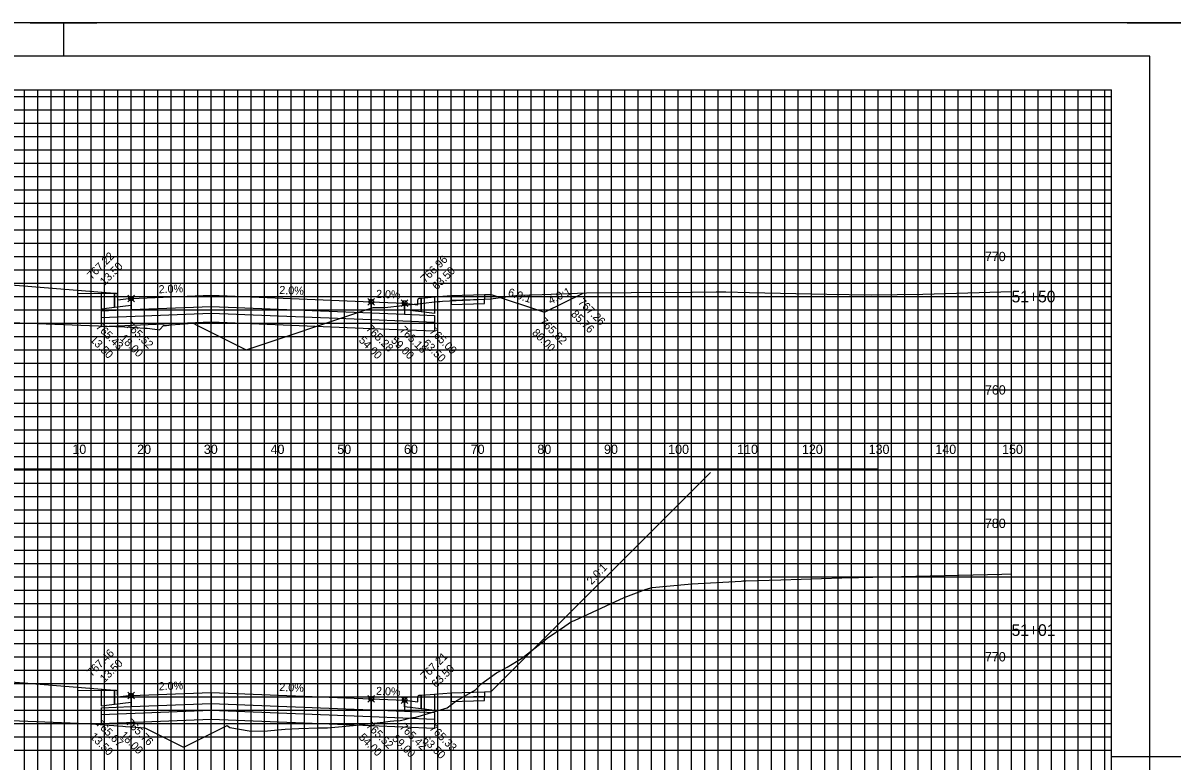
# Model space of a CAD drawing. Extents: x 578243 to 601557, y 174899 to 175559.
# Drawn here: x 601041.6 to 601213.9, y 175008.2 to 175118.8 of the extents above; entities that cross this region are included whole.
import ezdxf

# ---------------------------------------------------------------- set-up
doc = ezdxf.new("R2010")
doc.units = 0
for name, color, linetype in [('E_PROF_Grid', 7, 'Continuous'), ('E_PROF_GridMin', 7, 'Continuous'), ('P_CRDR_Label', 7, 'Continuous'), ('P_CRDR_Link', 7, 'Continuous'), ('P_E_XS_Ground', 7, 'Continuous'), ('P_RW_SlopeIntercepts', 7, 'Continuous'), ('P_XS_Text', 7, 'Continuous'), ('PLT_Sheet_Border', 7, 'Continuous'), ('PLT_Sheet_Info', 7, 'Continuous')]:
    doc.layers.add(name, color=color, linetype=linetype)

msp = doc.modelspace()

# ---------------------------------------------------------------- linework, layer by layer
at = {"layer": 'E_PROF_Grid'}
for p, q in [((601049.84, 174913.8), (601049.84, 175108.8)), ((601059.84, 174913.8), (601059.84, 175108.8)), ((601069.84, 174913.8), (601069.84, 175108.8)), ((601079.84, 174913.8), (601079.84, 175108.8)), ((601089.84, 174913.8), (601089.84, 175108.8)), ((601099.84, 174913.8), (601099.84, 175108.8)), ((601109.84, 174913.8), (601109.84, 175108.8)), ((601119.84, 174913.8), (601119.84, 175108.8)), ((601129.84, 174913.8), (601129.84, 175108.8)), ((601139.84, 174913.8), (601139.84, 175108.8)), ((601149.84, 174913.8), (601149.84, 175108.8)), ((601159.84, 174913.8), (601159.84, 175108.8)), ((601169.84, 174913.8), (601169.84, 175108.8)), ((601179.84, 174913.8), (601179.84, 175108.8)), ((601189.84, 174913.8), (601189.84, 175108.8)), ((601199.84, 174913.8), (601199.84, 175108.8)), ((600889.84, 175103.8), (601204.84, 175103.8)), ((600889.84, 175093.8), (601204.84, 175093.8)), ((600889.84, 175083.8), (601204.84, 175083.8)), ((600889.84, 175073.8), (601204.84, 175073.8)), ((600889.84, 175063.8), (601204.84, 175063.8)), ((600889.84, 175053.8), (601204.84, 175053.8)), ((600889.84, 175043.8), (601204.84, 175043.8)), ((600889.84, 175033.8), (601204.84, 175033.8)), ((600889.84, 175023.8), (601204.84, 175023.8)), ((600889.84, 175013.8), (601204.84, 175013.8))]:
    msp.add_line(p, q, dxfattribs=at)
at = {"layer": 'E_PROF_GridMin'}
for p, q in [((601041.84, 174913.8), (601041.84, 175108.8)), ((601043.84, 174913.8), (601043.84, 175108.8)), ((601045.84, 174913.8), (601045.84, 175108.8)), ((601047.84, 174913.8), (601047.84, 175108.8)), ((601051.84, 174913.8), (601051.84, 175108.8)), ((601053.84, 174913.8), (601053.84, 175108.8)), ((601055.84, 174913.8), (601055.84, 175108.8)), ((601057.84, 174913.8), (601057.84, 175108.8)), ((601061.84, 174913.8), (601061.84, 175108.8)), ((601063.84, 174913.8), (601063.84, 175108.8)), ((601065.84, 174913.8), (601065.84, 175108.8)), ((601067.84, 174913.8), (601067.84, 175108.8)), ((601071.84, 174913.8), (601071.84, 175108.8)), ((601073.84, 174913.8), (601073.84, 175108.8)), ((601075.84, 174913.8), (601075.84, 175108.8)), ((601077.84, 174913.8), (601077.84, 175108.8)), ((601081.84, 174913.8), (601081.84, 175108.8)), ((601083.84, 174913.8), (601083.84, 175108.8)), ((601085.84, 174913.8), (601085.84, 175108.8)), ((601087.84, 174913.8), (601087.84, 175108.8)), ((601091.84, 174913.8), (601091.84, 175108.8)), ((601093.84, 174913.8), (601093.84, 175108.8)), ((601095.84, 174913.8), (601095.84, 175108.8)), ((601097.84, 174913.8), (601097.84, 175108.8)), ((601101.84, 174913.8), (601101.84, 175108.8)), ((601103.84, 174913.8), (601103.84, 175108.8)), ((601105.84, 174913.8), (601105.84, 175108.8)), ((601107.84, 174913.8), (601107.84, 175108.8)), ((601111.84, 174913.8), (601111.84, 175108.8)), ((601113.84, 174913.8), (601113.84, 175108.8)), ((601115.84, 174913.8), (601115.84, 175108.8)), ((601117.84, 174913.8), (601117.84, 175108.8)), ((601121.84, 174913.8), (601121.84, 175108.8)), ((601123.84, 174913.8), (601123.84, 175108.8)), ((601125.84, 174913.8), (601125.84, 175108.8)), ((601127.84, 174913.8), (601127.84, 175108.8)), ((601131.84, 174913.8), (601131.84, 175108.8)), ((601133.84, 174913.8), (601133.84, 175108.8)), ((601135.84, 174913.8), (601135.84, 175108.8)), ((601137.84, 174913.8), (601137.84, 175108.8)), ((601141.84, 174913.8), (601141.84, 175108.8)), ((601143.84, 174913.8), (601143.84, 175108.8)), ((601145.84, 174913.8), (601145.84, 175108.8)), ((601147.84, 174913.8), (601147.84, 175108.8)), ((601151.84, 174913.8), (601151.84, 175108.8)), ((601153.84, 174913.8), (601153.84, 175108.8)), ((601155.84, 174913.8), (601155.84, 175108.8)), ((601157.84, 174913.8), (601157.84, 175108.8)), ((601161.84, 174913.8), (601161.84, 175108.8)), ((601163.84, 174913.8), (601163.84, 175108.8)), ((601165.84, 174913.8), (601165.84, 175108.8)), ((601167.84, 174913.8), (601167.84, 175108.8)), ((601171.84, 174913.8), (601171.84, 175108.8)), ((601173.84, 174913.8), (601173.84, 175108.8)), ((601175.84, 174913.8), (601175.84, 175108.8)), ((601177.84, 174913.8), (601177.84, 175108.8)), ((601181.84, 174913.8), (601181.84, 175108.8)), ((601183.84, 174913.8), (601183.84, 175108.8)), ((601185.84, 174913.8), (601185.84, 175108.8)), ((601187.84, 174913.8), (601187.84, 175108.8)), ((601191.84, 174913.8), (601191.84, 175108.8)), ((601193.84, 174913.8), (601193.84, 175108.8)), ((601195.84, 174913.8), (601195.84, 175108.8)), ((601197.84, 174913.8), (601197.84, 175108.8)), ((601201.84, 174913.8), (601201.84, 175108.8)), ((601203.84, 174913.8), (601203.84, 175108.8)), ((600889.84, 175107.8), (601204.84, 175107.8)), ((600889.84, 175105.8), (601204.84, 175105.8)), ((600889.84, 175101.8), (601204.84, 175101.8)), ((600889.84, 175099.8), (601204.84, 175099.8)), ((600889.84, 175097.8), (601204.84, 175097.8)), ((600889.84, 175095.8), (601204.84, 175095.8)), ((600889.84, 175091.8), (601204.84, 175091.8)), ((600889.84, 175089.8), (601204.84, 175089.8)), ((600889.84, 175087.8), (601204.84, 175087.8)), ((600889.84, 175085.8), (601204.84, 175085.8)), ((600889.84, 175081.8), (601204.84, 175081.8)), ((600889.84, 175079.8), (601204.84, 175079.8)), ((600889.84, 175077.8), (601204.84, 175077.8)), ((600889.84, 175075.8), (601204.84, 175075.8)), ((600889.84, 175071.8), (601204.84, 175071.8)), ((600889.84, 175069.8), (601204.84, 175069.8)), ((600889.84, 175067.8), (601204.84, 175067.8)), ((600889.84, 175065.8), (601204.84, 175065.8)), ((600889.84, 175061.8), (601204.84, 175061.8)), ((600889.84, 175059.8), (601204.84, 175059.8)), ((600889.84, 175057.8), (601204.84, 175057.8)), ((600889.84, 175055.8), (601204.84, 175055.8)), ((600889.84, 175051.8), (601204.84, 175051.8)), ((600889.84, 175049.8), (601204.84, 175049.8)), ((600889.84, 175047.8), (601204.84, 175047.8)), ((600889.84, 175045.8), (601204.84, 175045.8)), ((600889.84, 175041.8), (601204.84, 175041.8)), ((600889.84, 175039.8), (601204.84, 175039.8)), ((600889.84, 175037.8), (601204.84, 175037.8)), ((600889.84, 175035.8), (601204.84, 175035.8)), ((600889.84, 175031.8), (601204.84, 175031.8)), ((600889.84, 175029.8), (601204.84, 175029.8)), ((600889.84, 175027.8), (601204.84, 175027.8)), ((600889.84, 175025.8), (601204.84, 175025.8)), ((600889.84, 175021.8), (601204.84, 175021.8)), ((600889.84, 175019.8), (601204.84, 175019.8)), ((600889.84, 175017.8), (601204.84, 175017.8)), ((600889.84, 175015.8), (601204.84, 175015.8)), ((600889.84, 175011.8), (601204.84, 175011.8)), ((600889.84, 175009.8), (601204.84, 175009.8))]:
    msp.add_line(p, q, dxfattribs=at)
at = {"layer": 'P_CRDR_Label'}
for points in [[(601057.34, 175077), (601058.33, 175077.99)], [(601057.34, 175077.99), (601058.33, 175077)], [(601093.34, 175076.52), (601094.33, 175077.51)], [(601093.34, 175077.51), (601094.33, 175076.52)], [(601098.34, 175076.32), (601099.33, 175077.31)], [(601098.34, 175077.31), (601099.33, 175076.32)], [(601057.34, 175017.49), (601058.33, 175018.48)], [(601057.34, 175018.48), (601058.33, 175017.49)], [(601093.34, 175017.01), (601094.33, 175018)], [(601093.34, 175018), (601094.33, 175017.01)], [(601098.34, 175016.81), (601099.33, 175017.8)], [(601098.34, 175017.8), (601099.33, 175016.81)]]:
    msp.add_lwpolyline(points, dxfattribs=at)
for centre in [(601057.84, 175077.5), (601093.84, 175077.02), (601098.84, 175076.82), (601057.84, 175017.98), (601093.84, 175017.5), (601098.84, 175017.3)]:
    msp.add_circle(centre, 0.35, dxfattribs=at)
at = {"layer": 'P_CRDR_Link'}
msp.add_line((601144.69, 175051.44), (601111.84, 175018.59), dxfattribs=at)
for points in [[(601055.34, 175078.25), (601039.84, 175079.49)], [(601055.34, 175078.25), (601039.84, 175079.49)], [(601053.34, 175078.23), (601049.84, 175078.2)], [(601053.34, 175078.23), (601049.84, 175078.2)], [(601055.34, 175078.25), (601053.34, 175078.23)], [(601053.34, 175078.23), (601053.34, 175075.93)], [(601053.34, 175078.23), (601053.34, 175075.93)], [(601053.34, 175078.23), (601053.34, 175075.93)], [(601055.66, 175078.25), (601055.34, 175078.25)], [(601055.66, 175078.25), (601055.34, 175078.25)], [(601055.34, 175078.25), (601055.34, 175076.18)], [(601055.34, 175076.18), (601055.34, 175078.25)], [(601055.74, 175078.2), (601055.66, 175078.25)], [(601055.74, 175078.2), (601055.66, 175078.25)], [(601055.8, 175078.09), (601055.74, 175078.2)], [(601055.8, 175078.09), (601055.74, 175078.2)], [(601055.83, 175077.93), (601055.8, 175078.09)], [(601055.83, 175077.93), (601055.8, 175078.09)], [(601055.84, 175077.25), (601055.83, 175077.93)], [(601055.84, 175077.25), (601055.83, 175077.93)], [(601057.84, 175077.5), (601069.84, 175077.98)], [(601069.84, 175077.98), (601069.84, 175076.31)], [(601069.84, 175077.98), (601093.84, 175077.02)], [(601069.84, 175077.98), (601069.84, 175076.31)], [(601101.34, 175077.57), (601103.34, 175077.73)], [(601103.34, 175077.73), (601105.84, 175077.93)], [(601103.34, 175077.73), (601105.84, 175077.93)], [(601103.34, 175077.73), (601103.34, 175075.25)], [(601103.34, 175077.73), (601103.34, 175075.25)], [(601103.34, 175077.73), (601103.34, 175075.25)], [(601105.84, 175077.93), (601110.84, 175078.08)], [(601105.84, 175077.93), (601110.84, 175078.08)], [(601105.84, 175077.93), (601105.84, 175077.26)], [(601110.84, 175078.08), (601110.83, 175077.41)], [(601110.84, 175078.08), (601111.84, 175078.11)], [(601110.84, 175078.08), (601111.84, 175078.11)], [(601111.84, 175078.11), (601119.84, 175075.44)], [(601111.84, 175078.11), (601119.84, 175075.44)], [(601119.84, 175075.44), (601125.6, 175078.32)], [(601119.84, 175075.44), (601125.6, 175078.32)], [(601053.34, 175075.93), (601055.34, 175076.18)], [(601055.34, 175076.18), (601057.84, 175076.5)], [(601055.34, 175076.18), (601057.84, 175076.5)], [(601057.84, 175077.5), (601055.84, 175077.25)], [(601057.84, 175077.5), (601055.84, 175077.25)], [(601057.84, 175076.5), (601057.84, 175077.5)], [(601057.84, 175077.5), (601057.84, 175075.83)], [(601057.84, 175075.83), (601069.84, 175076.31)], [(601069.84, 175076.31), (601069.84, 175075.31)], [(601069.84, 175076.31), (601093.84, 175075.35)], [(601069.84, 175076.31), (601069.84, 175075.31)], [(601093.84, 175077.02), (601093.84, 175075.35)], [(601093.84, 175077.02), (601098.84, 175076.82)], [(601093.84, 175077.02), (601093.84, 175075.35)], [(601098.84, 175076.82), (601098.84, 175075.15)], [(601098.84, 175076.82), (601100.84, 175076.57)], [(601098.84, 175076.82), (601100.84, 175076.57)], [(601098.84, 175075.82), (601098.84, 175076.82)], [(601100.84, 175076.57), (601100.85, 175077.25)], [(601100.84, 175076.57), (601100.85, 175077.25)], [(601100.85, 175077.25), (601100.88, 175077.41)], [(601100.85, 175077.25), (601100.88, 175077.41)], [(601100.88, 175077.41), (601100.94, 175077.52)], [(601100.88, 175077.41), (601100.94, 175077.52)], [(601100.94, 175077.52), (601101.02, 175077.57)], [(601100.94, 175077.52), (601101.02, 175077.57)], [(601101.02, 175077.57), (601101.34, 175077.57)], [(601101.02, 175077.57), (601101.34, 175077.57)], [(601101.34, 175077.57), (601101.34, 175075.5)], [(601101.34, 175075.5), (601101.34, 175077.57)], [(601105.84, 175077.26), (601110.83, 175077.41)], [(601105.84, 175077.26), (601105.85, 175076.6)], [(601105.85, 175076.6), (601110.83, 175076.75)], [(601110.83, 175076.75), (601110.83, 175077.41)], [(601053.34, 175075.65), (601057.84, 175075.83)], [(601053.34, 175075.65), (601053.34, 175074.65)], [(601053.34, 175074.65), (601069.84, 175075.31)], [(601053.34, 175074.65), (601053.34, 175073.32)], [(601069.84, 175075.31), (601069.84, 175073.98)], [(601069.84, 175075.31), (601093.84, 175074.35)], [(601069.84, 175075.31), (601069.84, 175073.98)], [(601093.84, 175075.35), (601093.84, 175074.35)], [(601093.84, 175075.35), (601098.84, 175075.15)], [(601093.84, 175075.35), (601093.84, 175074.35)], [(601093.84, 175074.35), (601093.84, 175073.02)], [(601093.84, 175074.35), (601103.34, 175073.97)], [(601093.84, 175074.35), (601093.84, 175073.02)], [(601101.34, 175075.5), (601098.84, 175075.82)], [(601101.34, 175075.5), (601098.84, 175075.82)], [(601098.84, 175075.15), (601103.34, 175074.97)], [(601103.34, 175075.25), (601101.34, 175075.5)], [(601103.34, 175074.97), (601103.34, 175073.97)], [(601053.34, 175073.32), (601069.84, 175073.98)], [(601069.84, 175073.98), (601093.84, 175073.02)], [(601093.84, 175073.02), (601103.34, 175072.64)], [(601103.34, 175073.97), (601103.34, 175072.64)], [(601055.34, 175018.73), (601039.84, 175019.97)], [(601055.34, 175018.73), (601039.84, 175019.97)], [(601053.34, 175018.72), (601049.84, 175018.69)], [(601053.34, 175018.72), (601049.84, 175018.69)], [(601055.34, 175018.73), (601053.34, 175018.72)], [(601053.34, 175018.72), (601053.34, 175016.42)], [(601053.34, 175018.72), (601053.34, 175016.42)], [(601053.34, 175018.72), (601053.34, 175016.42)], [(601055.66, 175018.73), (601055.34, 175018.73)], [(601055.66, 175018.73), (601055.34, 175018.73)], [(601055.34, 175018.73), (601055.34, 175016.67)], [(601055.34, 175016.67), (601055.34, 175018.73)], [(601055.74, 175018.69), (601055.66, 175018.73)], [(601055.74, 175018.69), (601055.66, 175018.73)], [(601055.8, 175018.57), (601055.74, 175018.69)], [(601055.8, 175018.57), (601055.74, 175018.69)], [(601055.83, 175018.41), (601055.8, 175018.57)], [(601055.83, 175018.41), (601055.8, 175018.57)], [(601055.84, 175017.73), (601055.83, 175018.41)], [(601055.84, 175017.73), (601055.83, 175018.41)], [(601057.84, 175017.98), (601055.84, 175017.73)], [(601057.84, 175017.98), (601055.84, 175017.73)], [(601057.84, 175017.98), (601069.84, 175018.46)], [(601057.84, 175016.98), (601057.84, 175017.98)], [(601057.84, 175017.98), (601057.84, 175016.32)], [(601069.84, 175018.46), (601069.84, 175016.8)], [(601069.84, 175018.46), (601093.84, 175017.5)], [(601069.84, 175018.46), (601069.84, 175016.8)], [(601093.84, 175017.5), (601093.84, 175015.84)], [(601093.84, 175017.5), (601098.84, 175017.3)], [(601093.84, 175017.5), (601093.84, 175015.84)], [(601100.84, 175017.05), (601100.85, 175017.73)], [(601100.84, 175017.05), (601100.85, 175017.73)], [(601100.85, 175017.73), (601100.88, 175017.89)], [(601100.85, 175017.73), (601100.88, 175017.89)], [(601100.88, 175017.89), (601100.94, 175018.01)], [(601100.88, 175017.89), (601100.94, 175018.01)], [(601100.94, 175018.01), (601101.02, 175018.05)], [(601100.94, 175018.01), (601101.02, 175018.05)], [(601101.02, 175018.05), (601101.34, 175018.05)], [(601101.02, 175018.05), (601101.34, 175018.05)], [(601101.34, 175018.05), (601103.34, 175018.21)], [(601101.34, 175018.05), (601101.34, 175015.99)], [(601101.34, 175015.99), (601101.34, 175018.05)], [(601103.34, 175018.21), (601105.84, 175018.41)], [(601103.34, 175018.21), (601105.84, 175018.41)], [(601103.34, 175018.21), (601103.34, 175015.74)], [(601103.34, 175018.21), (601103.34, 175015.74)], [(601103.34, 175018.21), (601103.34, 175015.74)], [(601105.84, 175018.41), (601110.84, 175018.56)], [(601105.84, 175018.41), (601110.84, 175018.56)], [(601105.84, 175018.41), (601105.84, 175017.75)], [(601105.84, 175017.75), (601110.83, 175017.9)], [(601105.84, 175017.75), (601105.85, 175017.08)], [(601110.84, 175018.56), (601110.83, 175017.9)], [(601110.83, 175017.23), (601110.83, 175017.9)], [(601110.84, 175018.56), (601111.84, 175018.59)], [(601110.84, 175018.56), (601111.84, 175018.59)], [(601053.34, 175016.42), (601055.34, 175016.67)], [(601053.34, 175016.14), (601057.84, 175016.32)], [(601053.34, 175016.14), (601053.34, 175015.14)], [(601053.34, 175015.14), (601069.84, 175015.8)], [(601055.34, 175016.67), (601057.84, 175016.98)], [(601055.34, 175016.67), (601057.84, 175016.98)], [(601057.84, 175016.32), (601069.84, 175016.8)], [(601069.84, 175016.8), (601069.84, 175015.8)], [(601069.84, 175016.8), (601093.84, 175015.84)], [(601069.84, 175016.8), (601069.84, 175015.8)], [(601069.84, 175015.8), (601069.84, 175014.46)], [(601069.84, 175015.8), (601093.84, 175014.84)], [(601069.84, 175015.8), (601069.84, 175014.46)], [(601093.84, 175015.84), (601093.84, 175014.84)], [(601093.84, 175015.84), (601098.84, 175015.64)], [(601093.84, 175015.84), (601093.84, 175014.84)], [(601098.84, 175017.3), (601098.84, 175015.64)], [(601098.84, 175017.3), (601100.84, 175017.05)], [(601098.84, 175017.3), (601100.84, 175017.05)], [(601098.84, 175016.3), (601098.84, 175017.3)], [(601101.34, 175015.99), (601098.84, 175016.3)], [(601101.34, 175015.99), (601098.84, 175016.3)], [(601103.34, 175015.74), (601101.34, 175015.99)], [(601105.85, 175017.08), (601110.83, 175017.23)], [(601053.34, 175015.14), (601053.34, 175013.8)], [(601053.34, 175013.8), (601069.84, 175014.46)], [(601069.84, 175014.46), (601093.84, 175013.5)], [(601093.84, 175014.84), (601093.84, 175013.5)], [(601093.84, 175014.84), (601103.34, 175014.46)], [(601093.84, 175014.84), (601093.84, 175013.5)], [(601098.84, 175015.64), (601103.34, 175015.46)], [(601103.34, 175015.46), (601103.34, 175014.46)], [(601103.34, 175014.46), (601103.34, 175013.12)], [(601093.84, 175013.5), (601103.34, 175013.12)]]:
    msp.add_lwpolyline(points, dxfattribs=at)
at = {"layer": 'P_E_XS_Ground'}
for points in [[(601039.84, 175073.91), (601056.84, 175073.23), (601059.95, 175073.07), (601059.95, 175073.07), (601060.06, 175073.06), (601060.12, 175073.06), (601060.14, 175073.06), (601060.26, 175073.04), (601062.14, 175072.81), (601062.15, 175072.83), (601062.72, 175073.47), (601063.13, 175073.47), (601063.14, 175073.47), (601063.84, 175073.53), (601065.1, 175073.63), (601065.15, 175073.63), (601067.05, 175073.78), (601067.16, 175073.79), (601067.82, 175073.45), (601075.09, 175069.83), (601092.59, 175075.66), (601094.15, 175076.17), (601094.36, 175076.17), (601095.9, 175076.17), (601103.85, 175077.04), (601104.11, 175077.05), (601104.51, 175077.08), (601111.79, 175077.44), (601115.88, 175077.98), (601119.49, 175078.11), (601126.1, 175078.34), (601132.83, 175078.42), (601141.98, 175078.43), (601145.54, 175078.52), (601147, 175078.51), (601150.54, 175078.41), (601162.14, 175078.14), (601168.84, 175078.04), (601176.52, 175078.17), (601184.96, 175078.41), (601189.84, 175078.55)], [(601039.84, 175014.25), (601051.19, 175013.79), (601051.84, 175013.77), (601056.62, 175013.38), (601056.99, 175013.35), (601059.83, 175013.13), (601059.99, 175013.11), (601061.22, 175012.5), (601061.28, 175012.47), (601065.39, 175010.42), (601065.62, 175010.3), (601065.66, 175010.29), (601065.84, 175010.28), (601071.45, 175013.09), (601072.24, 175013.49), (601072.66, 175013.22), (601075.53, 175012.72), (601077.72, 175012.67), (601080.92, 175012.97), (601082.98, 175013.06), (601085.94, 175013.15), (601087.29, 175013.13), (601091.11, 175013.51), (601095.61, 175014.01), (601096.69, 175014.14), (601097.22, 175014.18), (601098.18, 175014.25), (601098.89, 175014.4), (601099.55, 175014.58), (601100.07, 175014.69), (601100.53, 175014.77), (601100.54, 175014.77), (601101.38, 175014.98), (601105.21, 175016.15), (601106.52, 175017.13), (601109.47, 175018.86), (601110.28, 175019.67), (601112.61, 175021.38), (601114.24, 175022.25), (601116.36, 175023.56), (601119.31, 175025.84), (601120.24, 175026.57), (601122.87, 175028.4), (601123.89, 175029.06), (601124.31, 175029.22), (601131.76, 175032.69), (601135.06, 175033.91), (601135.94, 175034.17), (601141.35, 175034.7), (601141.97, 175034.73), (601149.29, 175035.15), (601149.56, 175035.16), (601149.98, 175035.17), (601155.27, 175035.34), (601164.39, 175035.63), (601165.57, 175035.66), (601166.87, 175035.69), (601188.39, 175036.2), (601189.84, 175036.25)]]:
    msp.add_lwpolyline(points, dxfattribs=at)
at = {"layer": 'P_RW_SlopeIntercepts'}
msp.add_line((600933.84, 175051.96), (601169.84, 175051.96), dxfattribs=at)
at = {"layer": 'PLT_Sheet_Border'}
for points in [[(600877.19, 174898.8), (601217.19, 174898.8), (601217.19, 175118.8), (600877.19, 175118.8)], [(600879.59, 174903.8), (601210.59, 174903.8), (601210.59, 175113.8), (600879.59, 175113.8)]]:
    msp.add_lwpolyline(points, close=True, dxfattribs=at)
at = {"layer": 'PLT_Sheet_Info'}
for p, q in [((601042.69, 175118.8), (601052.69, 175118.8)), ((601047.69, 175118.8), (601047.69, 175113.8)), ((601207.19, 175118.8), (601217.19, 175118.8)), ((600889.84, 175108.8), (601204.84, 175108.8)), ((601204.84, 174908.8), (601204.84, 175108.8)), ((601217.19, 175008.8), (601204.84, 175008.8))]:
    msp.add_line(p, q, dxfattribs=at)

# ---------------------------------------------------------------- texts
at = {"layer": 'P_CRDR_Label'}
for s, rotation, p in [('767.22', 45, (601051.93, 175080.27)), ('13.50', 45, (601053.87, 175079.39)), ('766.96', 45, (601101.93, 175079.77)), ('63.50', 45, (601103.69, 175078.71)), ('2.0%', 2.2906, (601062, 175078.28)), ('2.0%', 357.7094, (601080.05, 175078.19)), ('2.0%', 357.7094, (601094.55, 175077.61)), ('6.0:1', 341.5651, (601114.24, 175077.96)), ('4.0:1', 26.5651, (601120.74, 175076.59)), ('767.26', 315, (601124.75, 175076.84)), ('767.26', 315, (601124.75, 175076.84)), ('765.82', 315, (601118.99, 175073.96)), ('85.76', 315, (601123.72, 175075.05)), ('85.76', 315, (601123.72, 175075.05)), ('765.43', 315, (601052.49, 175073.17)), ('765.52', 315, (601056.99, 175073.35)), ('765.28', 315, (601092.99, 175072.87)), ('765.18', 315, (601097.99, 175072.67)), ('765.09', 315, (601102.49, 175072.49)), ('80.00', 315, (601117.87, 175072.26)), ('13.50', 315, (601051.6, 175071.23)), ('18.00', 315, (601056.08, 175071.44)), ('54.00', 315, (601091.9, 175071.14)), ('59.00', 315, (601096.71, 175071.12)), ('63.50', 315, (601101.46, 175070.7)), ('2.0:1', 46.711, (601126.88, 175034.51)), ('767.46', 45, (601051.93, 175020.76)), ('767.21', 45, (601101.93, 175020.26)), ('13.50', 45, (601053.87, 175019.87)), ('63.50', 45, (601103.58, 175019.08)), ('2.0%', 2.2906, (601062, 175018.77)), ('2.0%', 357.7094, (601080.05, 175018.68)), ('2.0%', 357.7094, (601094.55, 175018.1)), ('765.67', 315, (601052.49, 175013.66)), ('765.76', 315, (601056.99, 175013.84)), ('765.52', 315, (601092.99, 175013.36)), ('13.50', 315, (601051.6, 175011.72)), ('18.00', 315, (601056.08, 175011.93)), ('54.00', 315, (601091.9, 175011.62)), ('765.42', 315, (601097.99, 175013.16)), ('765.33', 315, (601102.49, 175012.98)), ('59.00', 315, (601096.89, 175011.43)), ('63.50', 315, (601101.43, 175011.22))]:
    msp.add_text(s, height=1.2, rotation=rotation, dxfattribs=at).set_placement(p)
at = {"layer": 'P_XS_Text'}
for s, height, p in [('770', 1.4, (601185.84, 175083.1)), ('51+50', 1.75, (601189.84, 175076.92)), ('760', 1.4, (601185.84, 175063.1)), ('10', 1.4, (601049.04, 175054.2)), ('20', 1.4, (601058.75, 175054.2)), ('30', 1.4, (601068.75, 175054.2)), ('40', 1.4, (601078.75, 175054.2)), ('50', 1.4, (601088.75, 175054.2)), ('60', 1.4, (601098.75, 175054.2)), ('70', 1.4, (601108.75, 175054.2)), ('80', 1.4, (601118.75, 175054.2)), ('90', 1.4, (601128.74, 175054.2)), ('100', 1.4, (601138.36, 175054.2)), ('110', 1.4, (601148.7, 175054.2)), ('120', 1.4, (601158.41, 175054.2)), ('130', 1.4, (601168.41, 175054.2)), ('140', 1.4, (601178.41, 175054.2)), ('150', 1.4, (601188.41, 175054.2)), ('780', 1.4, (601185.84, 175043.1)), ('51+01', 1.75, (601189.84, 175026.92)), ('770', 1.4, (601185.84, 175023.1))]:
    msp.add_text(s, height=height, rotation=360, dxfattribs=at).set_placement(p)

doc.saveas('drawing.dxf')
